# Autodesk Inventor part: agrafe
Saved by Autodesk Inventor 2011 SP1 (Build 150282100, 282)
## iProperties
Created: 2010-12
Part Number: agrafe
Document SubType Name: Modeling
Designer: eric
Density: 1 g/cm^3
Author: eric
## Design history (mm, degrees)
feature "Base1"
node "Solide1"
node "Corps solides"
node "Corps surfaciques"
